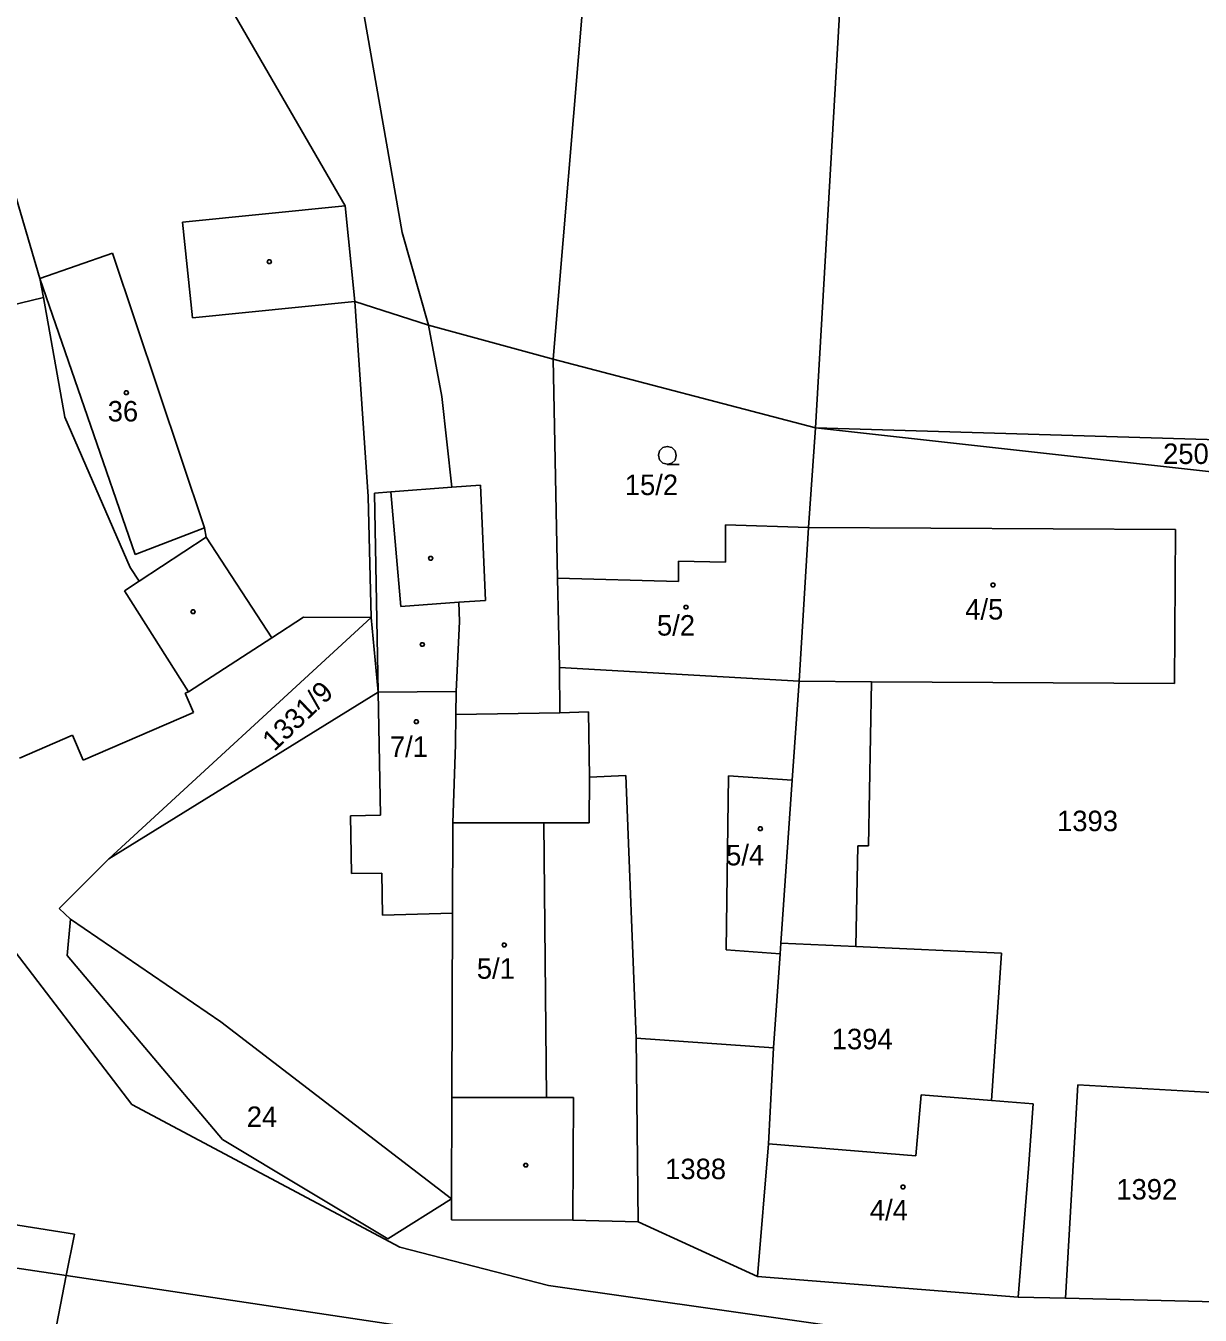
# Model space of a CAD drawing. Extents: x -852001 to -842497, y -1063614 to -1052182.
# Drawn here: x -844541.5 to -844444, y -1061468.2 to -1061361.2 of the extents above; entities that cross this region are included whole.
import ezdxf

# ---------------------------------------------------------------- set-up
doc = ezdxf.new("R2010")
doc.units = 0
for name, color, linetype in [('Default', 7, 'Continuous'), ('KN_HRANICE', 7, 'Continuous'), ('KN_KULTURY', 7, 'Continuous'), ('KN_PARCELY', 7, 'Continuous'), ('KN_SLUCKY', 7, 'Continuous')]:
    doc.layers.add(name, color=color, linetype=linetype)

# ---------------------------------------------------------------- blocks, each defined once
blk = doc.blocks.new('304')
at = {"layer": 'Default'}
blk.add_lwpolyline([(0, 0), (-0.38, 0.1), (-0.65, 0.37), (-0.75, 0.74), (-0.65, 1.11), (-0.38, 1.38), (-0.01, 1.48), (0.36, 1.38), (0.63, 1.11), (0.73, 0.73), (0.63, 0.35), (0.36, 0.08), (-0.02, -0.02), (0.98, -0.02)], dxfattribs=at)
blk = doc.blocks.new('402')
at = {"layer": 'Default'}
blk.add_lwpolyline([(0.09, 0.15), (0.18, 0), (0.09, -0.15), (-0.09, -0.15), (-0.18, 0), (-0.09, 0.15), (0.09, 0.15)], dxfattribs=at)

msp = doc.modelspace()

# ---------------------------------------------------------------- linework, layer by layer
at = {"layer": 'KN_HRANICE'}
for p, q in [((-844491.42, -1061312.67), (-844497.75, -1061388.86)), ((-844491.42, -1061312.67), (-844497.75, -1061388.86)), ((-844475.97, -1061394.54), (-844471.31, -1061313.26)), ((-844475.97, -1061394.54), (-844471.31, -1061313.26)), ((-844527.05, -1061355.32), (-844515.02, -1061376.12)), ((-844527.05, -1061355.32), (-844515.02, -1061376.12)), ((-844510.28, -1061378.35), (-844513.95, -1061357.42)), ((-844510.28, -1061378.35), (-844513.95, -1061357.42)), ((-844543.93, -1061370.06), (-844540.35, -1061382.16)), ((-844543.93, -1061370.06), (-844540.35, -1061382.16)), ((-844514.22, -1061384.06), (-844515.02, -1061376.12)), ((-844514.22, -1061384.06), (-844515.02, -1061376.12)), ((-844508.11, -1061386.03), (-844510.28, -1061378.35)), ((-844508.11, -1061386.03), (-844510.28, -1061378.35)), ((-844540.35, -1061382.16), (-844540.07, -1061383.72)), ((-844540.35, -1061382.16), (-844540.07, -1061383.72)), ((-844558.34, -1061388.2), (-844540.07, -1061383.72)), ((-844558.34, -1061388.2), (-844540.07, -1061383.72)), ((-844540.07, -1061383.72), (-844538.28, -1061393.67)), ((-844540.07, -1061383.72), (-844538.28, -1061393.67)), ((-844514.22, -1061384.06), (-844513.12, -1061400.25)), ((-844508.11, -1061386.03), (-844514.22, -1061384.06)), ((-844514.22, -1061384.06), (-844513.12, -1061400.25)), ((-844508.11, -1061386.03), (-844514.22, -1061384.06)), ((-844507, -1061391.95), (-844508.11, -1061386.03)), ((-844497.75, -1061388.86), (-844508.11, -1061386.03)), ((-844507, -1061391.95), (-844508.11, -1061386.03)), ((-844497.75, -1061388.86), (-844508.11, -1061386.03)), ((-844475.97, -1061394.54), (-844497.75, -1061388.86)), ((-844497.75, -1061388.86), (-844497.39, -1061407.02)), ((-844475.97, -1061394.54), (-844497.75, -1061388.86)), ((-844497.75, -1061388.86), (-844497.39, -1061407.02)), ((-844506.18, -1061399.48), (-844507, -1061391.95)), ((-844506.18, -1061399.48), (-844507, -1061391.95)), ((-844538.28, -1061393.67), (-844532.86, -1061406.15)), ((-844538.28, -1061393.67), (-844532.86, -1061406.15)), ((-844475.97, -1061394.54), (-844476.56, -1061402.81)), ((-844475.97, -1061394.54), (-844476.56, -1061402.81)), ((-844475.97, -1061394.54), (-844437.76, -1061395.7)), ((-844437.56, -1061398.83), (-844475.97, -1061394.54)), ((-844475.97, -1061394.54), (-844437.76, -1061395.7)), ((-844437.56, -1061398.83), (-844475.97, -1061394.54)), ((-844506.18, -1061399.48), (-844503.8, -1061399.32)), ((-844506.18, -1061399.48), (-844503.8, -1061399.32)), ((-844503.8, -1061399.32), (-844503.38, -1061408.87)), ((-844503.8, -1061399.32), (-844503.38, -1061408.87)), ((-844512.87, -1061410.29), (-844513.12, -1061400.25)), ((-844512.87, -1061410.29), (-844513.12, -1061400.25)), ((-844476.56, -1061402.81), (-844483.45, -1061402.59)), ((-844483.45, -1061402.59), (-844483.45, -1061405.7)), ((-844476.56, -1061402.81), (-844483.45, -1061402.59)), ((-844483.45, -1061402.59), (-844483.45, -1061405.7)), ((-844476.56, -1061402.81), (-844477.34, -1061415.58)), ((-844476.56, -1061402.81), (-844477.34, -1061415.58)), ((-844446.1, -1061402.99), (-844476.56, -1061402.81)), ((-844446.1, -1061402.99), (-844476.56, -1061402.81)), ((-844446.18, -1061415.77), (-844446.1, -1061402.99)), ((-844446.18, -1061415.77), (-844446.1, -1061402.99)), ((-844483.45, -1061405.7), (-844487.36, -1061405.61)), ((-844487.36, -1061405.61), (-844487.36, -1061407.3)), ((-844483.45, -1061405.7), (-844487.36, -1061405.61)), ((-844487.36, -1061405.61), (-844487.36, -1061407.3)), ((-844532.86, -1061406.15), (-844532.13, -1061407.28)), ((-844532.86, -1061406.15), (-844532.13, -1061407.28)), ((-844487.36, -1061407.3), (-844497.39, -1061407.02)), ((-844497.39, -1061407.02), (-844497.24, -1061414.43)), ((-844487.36, -1061407.3), (-844497.39, -1061407.02)), ((-844497.39, -1061407.02), (-844497.24, -1061414.43)), ((-844533.34, -1061408.07), (-844532.13, -1061407.28)), ((-844533.34, -1061408.07), (-844532.13, -1061407.28)), ((-844528.02, -1061416.46), (-844533.34, -1061408.07)), ((-844528.02, -1061416.46), (-844533.34, -1061408.07)), ((-844503.38, -1061408.87), (-844505.58, -1061409.03)), ((-844503.38, -1061408.87), (-844505.58, -1061409.03)), ((-844505.54, -1061410.63), (-844505.58, -1061409.03)), ((-844505.54, -1061410.63), (-844505.58, -1061409.03)), ((-844512.87, -1061410.29), (-844534.65, -1061430.32)), ((-844512.87, -1061410.29), (-844534.65, -1061430.32)), ((-844521.11, -1061411.99), (-844518.49, -1061410.26)), ((-844521.11, -1061411.99), (-844518.49, -1061410.26)), ((-844518.49, -1061410.26), (-844512.87, -1061410.29)), ((-844518.49, -1061410.26), (-844512.87, -1061410.29)), ((-844512.87, -1061410.29), (-844512.27, -1061416.48)), ((-844512.87, -1061410.29), (-844512.27, -1061416.48)), ((-844505.82, -1061416.42), (-844505.54, -1061410.63)), ((-844505.82, -1061416.42), (-844505.54, -1061410.63)), ((-844528.02, -1061416.46), (-844521.11, -1061411.99)), ((-844528.02, -1061416.46), (-844521.11, -1061411.99)), ((-844497.24, -1061414.43), (-844497.21, -1061418.2)), ((-844497.24, -1061414.43), (-844497.21, -1061418.2)), ((-844477.91, -1061423.8), (-844477.34, -1061415.58)), ((-844477.91, -1061423.8), (-844477.34, -1061415.58)), ((-844477.34, -1061415.58), (-844471.33, -1061415.62)), ((-844477.34, -1061415.58), (-844471.33, -1061415.62)), ((-844471.33, -1061415.62), (-844446.18, -1061415.77)), ((-844471.33, -1061415.62), (-844446.18, -1061415.77)), ((-844512.27, -1061416.48), (-844534.65, -1061430.32)), ((-844512.27, -1061416.48), (-844534.65, -1061430.32)), ((-844528.29, -1061416.58), (-844528.02, -1061416.46)), ((-844528.29, -1061416.58), (-844528.02, -1061416.46)), ((-844527.6, -1061418.16), (-844528.29, -1061416.58)), ((-844527.6, -1061418.16), (-844528.29, -1061416.58)), ((-844505.84, -1061418.35), (-844505.82, -1061416.42)), ((-844505.84, -1061418.35), (-844505.82, -1061416.42)), ((-844536.76, -1061422.14), (-844527.6, -1061418.16)), ((-844536.76, -1061422.14), (-844527.6, -1061418.16)), ((-844505.86, -1061420.82), (-844505.84, -1061418.35)), ((-844505.86, -1061420.82), (-844505.84, -1061418.35)), ((-844497.21, -1061418.2), (-844494.81, -1061418.12)), ((-844497.21, -1061418.2), (-844494.81, -1061418.12)), ((-844494.81, -1061418.12), (-844494.74, -1061423.55)), ((-844494.81, -1061418.12), (-844494.74, -1061423.55)), ((-844542.06, -1061421.97), (-844537.66, -1061420.06)), ((-844542.06, -1061421.97), (-844537.66, -1061420.06)), ((-844537.66, -1061420.06), (-844536.76, -1061422.14)), ((-844537.66, -1061420.06), (-844536.76, -1061422.14)), ((-844506.07, -1061427.33), (-844505.86, -1061420.82)), ((-844506.07, -1061427.33), (-844505.86, -1061420.82)), ((-844491.72, -1061423.39), (-844494.74, -1061423.55)), ((-844491.72, -1061423.39), (-844494.74, -1061423.55)), ((-844491.72, -1061423.39), (-844490.87, -1061445.21)), ((-844491.72, -1061423.39), (-844490.87, -1061445.21)), ((-844483.19, -1061423.43), (-844483.4, -1061437.88)), ((-844483.19, -1061423.43), (-844483.4, -1061437.88)), ((-844477.91, -1061423.8), (-844483.19, -1061423.43)), ((-844477.91, -1061423.8), (-844483.19, -1061423.43)), ((-844478.86, -1061437.32), (-844477.91, -1061423.8)), ((-844478.86, -1061437.32), (-844477.91, -1061423.8)), ((-844506.1, -1061434.82), (-844506.07, -1061427.33)), ((-844506.1, -1061434.82), (-844506.07, -1061427.33)), ((-844534.65, -1061430.32), (-844538.76, -1061434.44)), ((-844534.65, -1061430.32), (-844538.76, -1061434.44)), ((-844538.76, -1061434.44), (-844537.81, -1061435.32)), ((-844538.76, -1061434.44), (-844537.81, -1061435.32)), ((-844506.1, -1061434.82), (-844506.16, -1061450.12)), ((-844506.1, -1061434.82), (-844506.16, -1061450.12)), ((-844537.81, -1061435.32), (-844538.1, -1061438.35)), ((-844537.81, -1061435.32), (-844538.1, -1061438.35)), ((-844537.81, -1061435.32), (-844525.34, -1061443.83)), ((-844537.81, -1061435.32), (-844525.34, -1061443.83)), ((-844483.4, -1061437.88), (-844478.92, -1061438.19)), ((-844483.4, -1061437.88), (-844478.92, -1061438.19)), ((-844479.46, -1061446.01), (-844478.92, -1061438.19)), ((-844479.46, -1061446.01), (-844478.92, -1061438.19)), ((-844478.86, -1061437.32), (-844478.92, -1061438.19)), ((-844478.86, -1061437.32), (-844478.92, -1061438.19)), ((-844472.62, -1061437.6), (-844478.86, -1061437.32)), ((-844472.62, -1061437.6), (-844478.86, -1061437.32)), ((-844472.62, -1061437.6), (-844460.54, -1061438.15)), ((-844472.62, -1061437.6), (-844460.54, -1061438.15)), ((-844461.37, -1061450.37), (-844460.54, -1061438.15)), ((-844461.37, -1061450.37), (-844460.54, -1061438.15)), ((-844538.1, -1061438.35), (-844525.21, -1061453.61)), ((-844538.1, -1061438.35), (-844525.21, -1061453.61)), ((-844525.34, -1061443.83), (-844506.19, -1061458.53)), ((-844525.34, -1061443.83), (-844506.19, -1061458.53)), ((-844479.46, -1061446.01), (-844490.87, -1061445.21)), ((-844490.87, -1061445.21), (-844490.69, -1061460.43)), ((-844479.46, -1061446.01), (-844490.87, -1061445.21)), ((-844490.87, -1061445.21), (-844490.69, -1061460.43)), ((-844479.88, -1061453.98), (-844479.46, -1061446.01)), ((-844479.88, -1061453.98), (-844479.46, -1061446.01)), ((-844467.66, -1061454.96), (-844467.22, -1061449.89)), ((-844467.66, -1061454.96), (-844467.22, -1061449.89)), ((-844467.22, -1061449.89), (-844461.37, -1061450.37)), ((-844467.22, -1061449.89), (-844461.37, -1061450.37)), ((-844454.2, -1061449.07), (-844455.23, -1061466.77)), ((-844454.2, -1061449.07), (-844455.23, -1061466.77)), ((-844454.2, -1061449.07), (-844438.29, -1061449.97)), ((-844454.2, -1061449.07), (-844438.29, -1061449.97)), ((-844506.16, -1061450.12), (-844506.19, -1061458.53)), ((-844506.16, -1061450.12), (-844506.19, -1061458.53)), ((-844461.37, -1061450.37), (-844457.92, -1061450.65)), ((-844461.37, -1061450.37), (-844457.92, -1061450.65)), ((-844458.3, -1061456.01), (-844457.92, -1061450.65)), ((-844458.3, -1061456.01), (-844457.92, -1061450.65)), ((-844525.21, -1061453.61), (-844511.48, -1061461.86)), ((-844525.21, -1061453.61), (-844511.48, -1061461.86)), ((-844480.79, -1061464.98), (-844479.88, -1061453.98)), ((-844480.79, -1061464.98), (-844479.88, -1061453.98)), ((-844467.66, -1061454.96), (-844479.88, -1061453.98)), ((-844467.66, -1061454.96), (-844479.88, -1061453.98)), ((-844459.17, -1061466.7), (-844458.3, -1061456.01)), ((-844459.17, -1061466.7), (-844458.3, -1061456.01)), ((-844511.48, -1061461.86), (-844506.19, -1061458.53)), ((-844511.48, -1061461.86), (-844506.19, -1061458.53)), ((-844506.19, -1061458.53), (-844506.2, -1061460.27)), ((-844506.19, -1061458.53), (-844506.2, -1061460.27)), ((-844544.65, -1061460.34), (-844537.49, -1061461.47)), ((-844544.65, -1061460.34), (-844537.49, -1061461.47)), ((-844506.2, -1061460.27), (-844496.12, -1061460.31)), ((-844506.2, -1061460.27), (-844496.12, -1061460.31)), ((-844490.69, -1061460.43), (-844496.12, -1061460.31)), ((-844490.69, -1061460.43), (-844496.12, -1061460.31)), ((-844490.69, -1061460.43), (-844480.79, -1061464.98)), ((-844490.69, -1061460.43), (-844480.79, -1061464.98)), ((-844537.49, -1061461.47), (-844538.17, -1061464.9)), ((-844537.49, -1061461.47), (-844538.17, -1061464.9)), ((-844538.17, -1061464.9), (-844540.06, -1061474.46)), ((-844538.17, -1061464.9), (-844540.06, -1061474.46)), ((-844480.79, -1061464.98), (-844459.17, -1061466.7)), ((-844480.79, -1061464.98), (-844459.17, -1061466.7)), ((-844455.23, -1061466.77), (-844459.17, -1061466.7)), ((-844455.23, -1061466.77), (-844459.17, -1061466.7)), ((-844439.9, -1061467.16), (-844455.23, -1061466.77)), ((-844439.9, -1061467.16), (-844455.23, -1061466.77))]:
    msp.add_line(p, q, dxfattribs=at)
at = {"layer": 'KN_SLUCKY'}
for p, q in [((-844515.02, -1061376.12), (-844528.52, -1061377.48)), ((-844515.02, -1061376.12), (-844528.52, -1061377.48)), ((-844528.52, -1061377.48), (-844527.69, -1061385.41)), ((-844528.52, -1061377.48), (-844527.69, -1061385.41)), ((-844534.32, -1061380.05), (-844540.35, -1061382.16)), ((-844534.32, -1061380.05), (-844540.35, -1061382.16)), ((-844526.69, -1061402.86), (-844534.32, -1061380.05)), ((-844526.69, -1061402.86), (-844534.32, -1061380.05)), ((-844540.35, -1061382.16), (-844532.45, -1061405.06)), ((-844540.35, -1061382.16), (-844532.45, -1061405.06)), ((-844527.69, -1061385.41), (-844514.22, -1061384.06)), ((-844527.69, -1061385.41), (-844514.22, -1061384.06)), ((-844511.22, -1061399.86), (-844506.18, -1061399.48)), ((-844511.22, -1061399.86), (-844506.18, -1061399.48)), ((-844512.59, -1061399.96), (-844511.22, -1061399.86)), ((-844512.59, -1061399.96), (-844511.22, -1061399.86)), ((-844512.27, -1061416.48), (-844512.59, -1061399.96)), ((-844512.27, -1061416.48), (-844512.59, -1061399.96)), ((-844510.4, -1061409.39), (-844511.22, -1061399.86)), ((-844510.4, -1061409.39), (-844511.22, -1061399.86)), ((-844532.45, -1061405.06), (-844526.69, -1061402.86)), ((-844532.45, -1061405.06), (-844526.69, -1061402.86)), ((-844526.55, -1061403.62), (-844526.69, -1061402.86)), ((-844526.55, -1061403.62), (-844526.69, -1061402.86)), ((-844532.13, -1061407.28), (-844526.55, -1061403.62)), ((-844532.13, -1061407.28), (-844526.55, -1061403.62)), ((-844521.11, -1061411.99), (-844526.55, -1061403.62)), ((-844521.11, -1061411.99), (-844526.55, -1061403.62)), ((-844505.58, -1061409.03), (-844510.4, -1061409.39)), ((-844505.58, -1061409.03), (-844510.4, -1061409.39)), ((-844477.34, -1061415.58), (-844497.24, -1061414.43)), ((-844477.34, -1061415.58), (-844497.24, -1061414.43)), ((-844471.57, -1061429.24), (-844471.33, -1061415.62)), ((-844471.57, -1061429.24), (-844471.33, -1061415.62)), ((-844512.27, -1061416.48), (-844505.82, -1061416.42)), ((-844512.27, -1061416.48), (-844505.82, -1061416.42)), ((-844512.27, -1061416.48), (-844512.08, -1061426.69)), ((-844512.27, -1061416.48), (-844512.08, -1061426.69)), ((-844532.72, -1061450.71), (-844558.62, -1061416.89)), ((-844532.72, -1061450.71), (-844558.62, -1061416.89)), ((-844497.21, -1061418.2), (-844505.84, -1061418.35)), ((-844497.21, -1061418.2), (-844505.84, -1061418.35)), ((-844494.78, -1061427.32), (-844494.74, -1061423.55)), ((-844494.78, -1061427.32), (-844494.74, -1061423.55)), ((-844512.08, -1061426.69), (-844514.58, -1061426.74)), ((-844512.08, -1061426.69), (-844514.58, -1061426.74)), ((-844514.58, -1061426.74), (-844514.49, -1061431.54)), ((-844514.58, -1061426.74), (-844514.49, -1061431.54)), ((-844506.07, -1061427.33), (-844498.54, -1061427.32)), ((-844506.07, -1061427.33), (-844498.54, -1061427.32)), ((-844498.54, -1061427.32), (-844494.78, -1061427.32)), ((-844498.31, -1061450.11), (-844498.54, -1061427.32)), ((-844498.54, -1061427.32), (-844494.78, -1061427.32)), ((-844498.31, -1061450.11), (-844498.54, -1061427.32)), ((-844472.62, -1061437.6), (-844472.47, -1061429.23)), ((-844472.62, -1061437.6), (-844472.47, -1061429.23)), ((-844472.47, -1061429.23), (-844471.57, -1061429.24)), ((-844472.47, -1061429.23), (-844471.57, -1061429.24)), ((-844514.49, -1061431.54), (-844511.99, -1061431.5)), ((-844514.49, -1061431.54), (-844511.99, -1061431.5)), ((-844511.99, -1061431.5), (-844511.92, -1061435)), ((-844511.99, -1061431.5), (-844511.92, -1061435)), ((-844511.92, -1061435), (-844506.1, -1061434.82)), ((-844511.92, -1061435), (-844506.1, -1061434.82)), ((-844510.47, -1061462.54), (-844532.72, -1061450.71)), ((-844510.47, -1061462.54), (-844532.72, -1061450.71)), ((-844498.31, -1061450.11), (-844506.16, -1061450.12)), ((-844498.31, -1061450.11), (-844506.16, -1061450.12)), ((-844496.08, -1061450.13), (-844498.31, -1061450.11)), ((-844496.08, -1061450.13), (-844498.31, -1061450.11)), ((-844496.12, -1061460.31), (-844496.08, -1061450.13)), ((-844496.12, -1061460.31), (-844496.08, -1061450.13)), ((-844558.37, -1061461.86), (-844538.17, -1061464.9)), ((-844558.37, -1061461.86), (-844538.17, -1061464.9)), ((-844510.47, -1061462.54), (-844498.15, -1061465.73)), ((-844510.47, -1061462.54), (-844498.15, -1061465.73)), ((-844538.17, -1061464.9), (-844509.4, -1061469.22)), ((-844538.17, -1061464.9), (-844509.4, -1061469.22)), ((-844498.15, -1061465.73), (-844469.55, -1061469.78)), ((-844498.15, -1061465.73), (-844469.55, -1061469.78))]:
    msp.add_line(p, q, dxfattribs=at)

# ---------------------------------------------------------------- block references
at = {"layer": 'KN_KULTURY'}
for name, p in [('402', (-844521.32, -1061380.76)), ('402', (-844521.32, -1061380.76)), ('402', (-844533.18, -1061391.64)), ('402', (-844533.18, -1061391.64)), ('304', (-844488.27, -1061397.57)), ('304', (-844488.27, -1061397.57)), ('402', (-844507.92, -1061405.37)), ('402', (-844507.92, -1061405.37)), ('402', (-844461.25, -1061407.59)), ('402', (-844461.25, -1061407.59)), ('402', (-844486.73, -1061409.43)), ('402', (-844486.73, -1061409.43)), ('402', (-844527.64, -1061409.81)), ('402', (-844527.64, -1061409.81)), ('402', (-844508.62, -1061412.53)), ('402', (-844508.62, -1061412.53)), ('402', (-844509.11, -1061418.94)), ('402', (-844509.11, -1061418.94)), ('402', (-844480.56, -1061427.82)), ('402', (-844480.56, -1061427.82)), ('402', (-844501.82, -1061437.46)), ('402', (-844501.82, -1061437.46)), ('402', (-844500.03, -1061455.74)), ('402', (-844500.03, -1061455.74)), ('402', (-844468.72, -1061457.55)), ('402', (-844468.72, -1061457.55))]:
    msp.add_blockref(name, p, dxfattribs=at)

# ---------------------------------------------------------------- texts
at = {"layer": 'KN_PARCELY'}
for s, p in [('36', (-844534.73, -1061394.02)), ('36', (-844534.73, -1061394.02)), ('250/3', (-844447.13, -1061397.55)), ('250/3', (-844447.13, -1061397.55)), ('15/2', (-844491.81, -1061400.13)), ('15/2', (-844491.81, -1061400.13)), ('4/5', (-844463.55, -1061410.46)), ('4/5', (-844463.55, -1061410.46)), ('5/2', (-844489.14, -1061411.79)), ('5/2', (-844489.14, -1061411.79)), ('7/1', (-844511.31, -1061421.86)), ('7/1', (-844511.31, -1061421.86)), ('1393', (-844455.93, -1061428.02)), ('1393', (-844455.93, -1061428.02)), ('5/4', (-844483.4, -1061430.86)), ('5/4', (-844483.4, -1061430.86)), ('5/1', (-844504.09, -1061440.27)), ('5/1', (-844504.09, -1061440.27)), ('1394', (-844474.63, -1061446.12)), ('1394', (-844474.63, -1061446.12)), ('24', (-844523.19, -1061452.57)), ('24', (-844523.19, -1061452.57)), ('1388', (-844488.46, -1061456.9)), ('1388', (-844488.46, -1061456.9)), ('1392', (-844451.01, -1061458.59)), ('1392', (-844451.01, -1061458.59)), ('4/4', (-844471.47, -1061460.32)), ('4/4', (-844471.47, -1061460.32))]:
    msp.add_text(s, height=1.7, dxfattribs=at).set_placement(p)
msp.add_text('1331/9', height=1.7, rotation=43.717, dxfattribs=at).set_placement((-844520.9, -1061421.46))
msp.add_text('1331/9', height=1.7, rotation=43.717, dxfattribs=at).set_placement((-844520.9, -1061421.46))

doc.saveas('drawing.dxf')
